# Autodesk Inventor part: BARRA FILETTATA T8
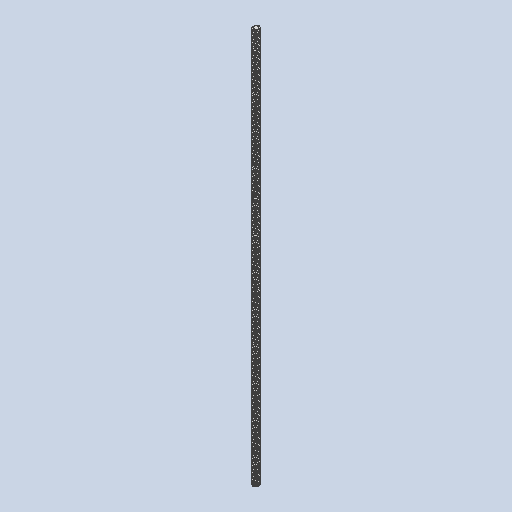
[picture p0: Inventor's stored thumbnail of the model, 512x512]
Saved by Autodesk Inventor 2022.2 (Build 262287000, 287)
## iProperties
Created: 2024-09
Part Number: BARRA FILETTATA T8
Material: Generico
Document SubType Name: Modeling
Designer: 18907419
Density: 1 g/cm^3
Appearance: Default
Author: 18907419
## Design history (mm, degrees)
feature "Solido1"
node "Solido2"
